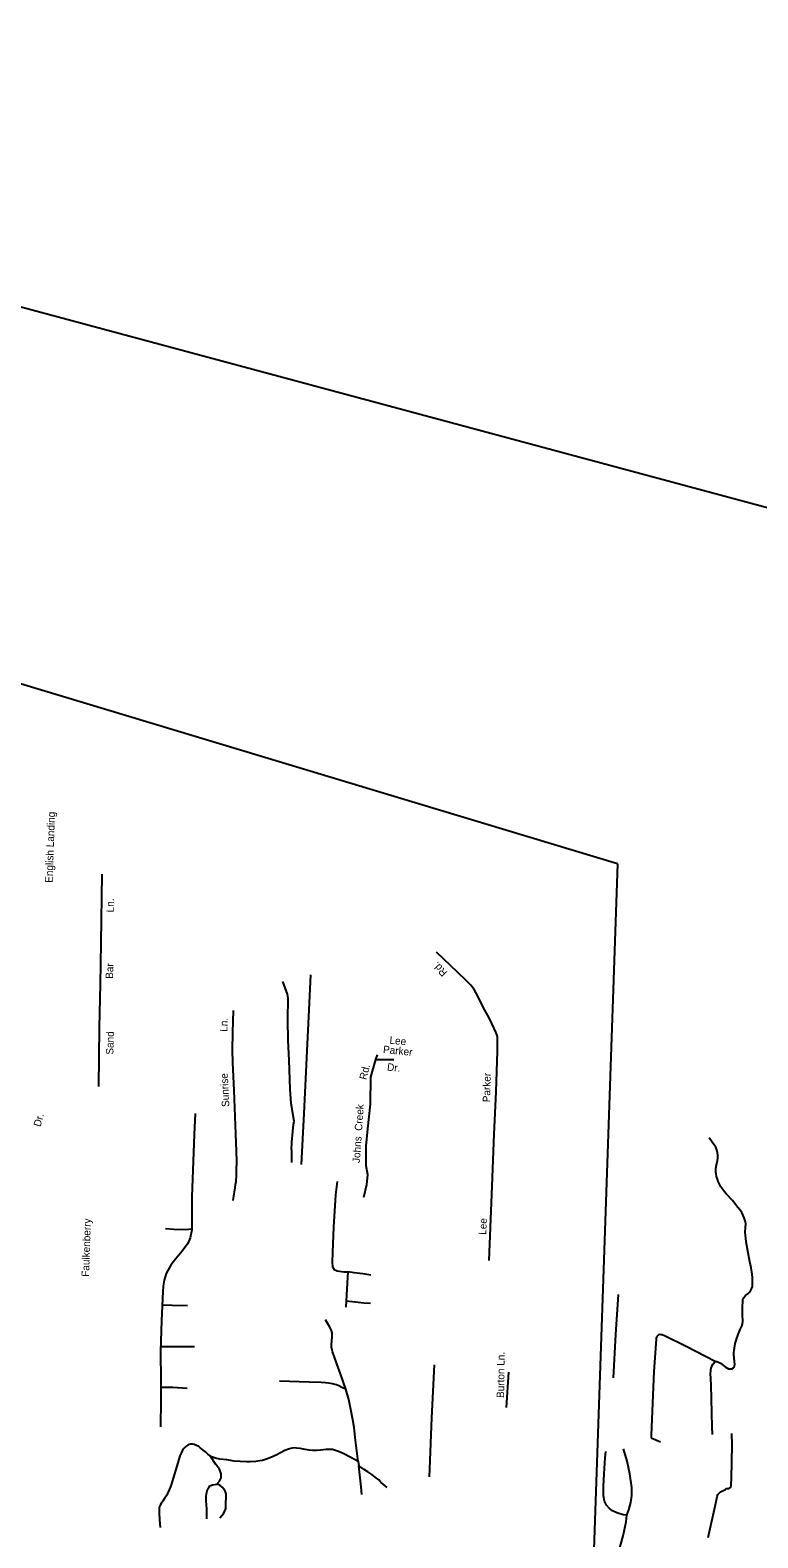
# Model space of a CAD drawing. Extents: x 2308163 to 2335412, y -96774 to 125428.
# Drawn here: x 2320371 to 2321170, y 14013 to 15668 of the extents above; entities that cross this region are included whole.
import ezdxf

# ---------------------------------------------------------------- set-up
doc = ezdxf.new("R2010")
doc.units = 0
for name, color, linetype in [('Old_Level_10', 7, 'Continuous'), ('Old_Level_35', 7, 'Continuous'), ('Old_Level_63', 7, 'Continuous')]:
    doc.layers.add(name, color=color, linetype=linetype)

msp = doc.modelspace()

# ---------------------------------------------------------------- linework, layer by layer
at = {"layer": 'Old_Level_35'}
for p, q in [((2321052.8, 14125.9), (2321052.7, 14123)), ((2321052.7, 14123), (2321063.1, 14118.8)), ((2321119.9, 14126.6), (2321119.6, 14135.1)), ((2320731.1, 14097), (2320731.8, 14092.3)), ((2320734.4, 14069.4), (2320731.8, 14092.3)), ((2320809.5, 14080.2), (2320809.8, 14088.9)), ((2320735.3, 14060.9), (2320734.4, 14069.4)), ((2320513.4, 14033.1), (2320513.8, 14024.7))]:
    msp.add_line(p, q, dxfattribs=at)
for points in [[(2320446.5, 14508.6), (2320447.5, 14573.6), (2320448.4, 14621.1), (2320449.3, 14666.6), (2320450.3, 14741.8)], [(2320874.8, 14317.9), (2320877.8, 14390.1), (2320880.4, 14456.3), (2320882.6, 14503), (2320884.1, 14547.5), (2320884.1, 14551.2), (2320884.1, 14555.6), (2320884.2, 14560), (2320884, 14563), (2320883.6, 14564.8), (2320882.4, 14568.3), (2320880.5, 14572.6), (2320875.2, 14583.3), (2320870.2, 14592.6), (2320860.4, 14612.1), (2320858.6, 14615.4), (2320854.9, 14620), (2320849.5, 14625.6), (2320840.7, 14633.9), (2320817, 14656.2)], [(2320658.3, 14425.4), (2320658.3, 14437.2), (2320658.2, 14441.9), (2320658.5, 14444.9), (2320658.6, 14447.7), (2320659.6, 14459.4), (2320660.1, 14466.9), (2320660.9, 14470.9), (2320657.8, 14490.2), (2320656.7, 14506), (2320655.5, 14537.8), (2320654.3, 14559.3), (2320653.9, 14582.3), (2320654.4, 14605.8), (2320653.5, 14610.1), (2320648.6, 14624)], [(2320669.2, 14423.2), (2320671.9, 14479), (2320675.3, 14548), (2320677.4, 14592.9), (2320679.1, 14631.4)], [(2320596.8, 14456.7), (2320595.2, 14504.5), (2320593.7, 14535), (2320593.2, 14548.6), (2320593.7, 14568), (2320594.5, 14592.3)], [(2320752, 14543.7), (2320750.3, 14538.4), (2320747.4, 14528.3), (2320744.8, 14518.9), (2320744.4, 14489.4), (2320741.6, 14462.2), (2320739.7, 14443.3), (2320739.6, 14422.1), (2320741.5, 14412.2), (2320740.4, 14400.8), (2320736.9, 14386.8)], [(2320750.3, 14538.4), (2320770.3, 14538.3)], [(2320552.3, 14479.2), (2320551.1, 14455.9), (2320548.8, 14387.6), (2320548.6, 14360.5), (2320548.6, 14351.6), (2320546.9, 14342.5), (2320544.2, 14336.4), (2320538.2, 14328.1), (2320530.7, 14319.1), (2320525.5, 14312.8), (2320520.6, 14303.6), (2320518.5, 14296), (2320517.1, 14289.7), (2320516.9, 14283.6), (2320515.4, 14251.7), (2320514.4, 14217.7), (2320514.7, 14185.6), (2320514.7, 14164.3), (2320514.4, 14135.1)], [(2320594, 14383.7), (2320595.2, 14390.9), (2320596.4, 14397.4), (2320596.7, 14401.2), (2320597.3, 14404.4), (2320597.7, 14411.9), (2320597.8, 14417.1), (2320598.1, 14426.8), (2320597.8, 14437.4), (2320596.8, 14456.7)], [(2321123, 14206.8), (2321123.7, 14206.8), (2321124.8, 14206.9), (2321126.5, 14206.3), (2321128.7, 14205.2), (2321130.2, 14203.9), (2321133.9, 14201.1), (2321135.8, 14199.8), (2321137.5, 14199), (2321139.5, 14198.7), (2321141.3, 14198.9), (2321142.9, 14199.9), (2321143.6, 14200.8), (2321144.1, 14202.2), (2321144.5, 14203.6), (2321143.4, 14214.1), (2321143.5, 14216.9), (2321143.6, 14218.9), (2321144.4, 14224.1), (2321145, 14226.6), (2321145.8, 14230.1), (2321146.6, 14232.5), (2321147.7, 14235.3), (2321149, 14238.5), (2321150.5, 14241.9), (2321152.2, 14245.7), (2321153, 14248.4), (2321153.3, 14250.7), (2321153.1, 14252.7), (2321153, 14256.9), (2321152.9, 14261.4), (2321153, 14267.4), (2321153.1, 14272.4), (2321153.4, 14274.4), (2321153.6, 14276), (2321154.3, 14277.3), (2321156.3, 14279.3), (2321158.6, 14281.3), (2321160.4, 14283), (2321161.9, 14285.2), (2321163, 14287.3), (2321163.7, 14289.3), (2321163.9, 14291.9), (2321163.9, 14294.7), (2321163.7, 14298.7), (2321163.4, 14302.7), (2321162.3, 14309.7), (2321160.9, 14316.2), (2321159.2, 14326.3), (2321156.9, 14338.4), (2321156.4, 14342.2), (2321156.1, 14345.1), (2321156, 14348.9), (2321156.3, 14354.1), (2321156.4, 14357.9), (2321156.2, 14360.1), (2321155.5, 14362.4), (2321154.7, 14364.5), (2321153.6, 14367), (2321152, 14370.3), (2321150.3, 14373), (2321147.9, 14376.1), (2321142, 14383.5), (2321135.4, 14390.6), (2321133.3, 14393.2), (2321131.3, 14395.7), (2321129.2, 14398.8), (2321127.6, 14401.5), (2321126.2, 14404.5), (2321125.4, 14406.9), (2321124.4, 14410.1), (2321124, 14412.9), (2321123.8, 14414.9), (2321123.8, 14418.7), (2321124.2, 14422.7), (2321125.3, 14427.7), (2321125.8, 14430.1), (2321125.9, 14433.5), (2321125.5, 14435.9), (2321124.6, 14439.4), (2321123.7, 14442.2), (2321119.6, 14447.8), (2321116.2, 14452.6)], [(2320708, 14404.3), (2320706.4, 14390), (2320704.2, 14354.3), (2320702.9, 14327), (2320702.6, 14316), (2320703, 14310.8), (2320704.9, 14307.8), (2320708.1, 14306.4), (2320715.5, 14305.4), (2320719.8, 14305.3)], [(2320548.6, 14352.3), (2320542, 14351.4), (2320528.9, 14351.8), (2320519.7, 14352.6)], [(2320719.8, 14305.3), (2320718.8, 14286.8), (2320717.5, 14266.7)], [(2320745, 14301.8), (2320736.3, 14303.1), (2320726.9, 14304.1), (2320719.8, 14305.3)], [(2320516.2, 14268.9), (2320527.3, 14268.8), (2320543.9, 14268.2)], [(2320717.9, 14273.3), (2320728.4, 14272.5), (2320737.5, 14271.2), (2320744.6, 14271)], [(2321011.5, 14189), (2321013.9, 14236.5), (2321016.7, 14280.5)], [(2320717.8, 14176.4), (2320712, 14193.3), (2320707.7, 14204.2), (2320704.7, 14212.6), (2320703.6, 14215.8), (2320703.1, 14218), (2320702.7, 14219.3), (2320702.1, 14222.5), (2320702, 14225.6), (2320702.3, 14229.5), (2320702.7, 14233.5), (2320702.7, 14235.8), (2320702.5, 14238.2), (2320701.9, 14240.8), (2320700.2, 14244.6), (2320697.5, 14248.9), (2320695.2, 14252.5)], [(2321123, 14206.8), (2321091.1, 14223.4), (2321067.4, 14235), (2321064.9, 14236), (2321063.7, 14236.3), (2321062.3, 14236.4), (2321060.7, 14236), (2321059.6, 14235.1), (2321058.9, 14234.2), (2321058.3, 14232.5), (2321058.3, 14231.4), (2321055.7, 14196), (2321052.8, 14125.9)], [(2320514.6, 14223.2), (2320525.8, 14223.4), (2320551.6, 14223.4)], [(2320809.8, 14088.9), (2320812.1, 14144.9), (2320814.8, 14203.3)], [(2321119.6, 14135.1), (2321118.4, 14181.2), (2321117.9, 14194), (2321118, 14196.2), (2321118.1, 14198.1), (2321118.8, 14200.5), (2321119.6, 14202.2), (2321120.4, 14203.9), (2321123, 14206.8)], [(2320717.8, 14176.4), (2320713.4, 14178.5), (2320710.1, 14180.1), (2320707.6, 14181.1), (2320702.9, 14182.5), (2320698.7, 14183.1), (2320695.2, 14183.4), (2320690.5, 14183.8), (2320677.5, 14184.1), (2320645, 14185.2)], [(2320894, 14156.3), (2320896.5, 14195)], [(2320543.4, 14177.3), (2320527.7, 14178.3), (2320514.7, 14178.4)], [(2320731.1, 14097), (2320727.8, 14123.6), (2320726.8, 14134.4), (2320725.5, 14142.7), (2320723.3, 14154.3), (2320720.8, 14165.3), (2320717.8, 14176.4)], [(2321115.3, 14013.7), (2321123.7, 14051.5), (2321125, 14058.7), (2321126, 14061), (2321127.5, 14062.7), (2321128.8, 14063.7), (2321130.1, 14064.4), (2321132.1, 14065.3), (2321134.1, 14066.3), (2321135.6, 14067.3), (2321136.2, 14067.4), (2321137.6, 14067.6), (2321139, 14068.2), (2321140, 14069), (2321140.4, 14071.2), (2321141, 14078.9), (2321141.7, 14114.9), (2321141.1, 14128)], [(2320563.8, 14107.6), (2320561.1, 14109.7), (2320559.1, 14111.2), (2320557.9, 14112.2), (2320556.2, 14113.5), (2320553.9, 14114.7), (2320551.2, 14115.6), (2320549.7, 14116.1), (2320547.3, 14116.2), (2320545.8, 14115.8), (2320544.2, 14115.1), (2320542.2, 14113.6), (2320539.9, 14111.4), (2320538.6, 14109.7), (2320537.2, 14106.8), (2320535.7, 14103.3), (2320533.3, 14095.8), (2320527.3, 14075.2), (2320525.6, 14070.3), (2320523.9, 14065.8), (2320522, 14061.8), (2320521.1, 14060.1), (2320518.8, 14056.4), (2320516.7, 14053.4), (2320515.2, 14051), (2320513.9, 14049.2), (2320513.3, 14047.8), (2320512.8, 14045.8), (2320512.7, 14044.1), (2320512.9, 14040.8), (2320513.4, 14033.1)], [(2320731.1, 14097), (2320723.3, 14101.3), (2320714.8, 14105.7), (2320709.6, 14108.1), (2320705.4, 14109.7), (2320703, 14110.3), (2320700, 14110.3), (2320696.2, 14110.1), (2320689.9, 14109.5), (2320685.4, 14109.3), (2320681.1, 14109.2), (2320677.4, 14109.6), (2320672.9, 14110.2), (2320667.7, 14111.3), (2320663.5, 14111.9), (2320660.4, 14112), (2320657.4, 14111.3), (2320654.9, 14110.6), (2320650.7, 14109), (2320646.1, 14106.6), (2320642, 14104.5), (2320638, 14102.5), (2320633.7, 14100.6), (2320630.7, 14099.5), (2320626.4, 14098.3), (2320623.4, 14097.9), (2320619.1, 14097.2), (2320612.8, 14096.8), (2320608.7, 14096.8), (2320601.6, 14097), (2320595.1, 14097.6), (2320587.1, 14098.8), (2320579.4, 14099.7), (2320574.6, 14100.6), (2320572.5, 14101.3), (2320570.4, 14102.2), (2320568.7, 14103.2), (2320566.3, 14105), (2320563.8, 14107.6)], [(2320579.5, 14035.2), (2320583.9, 14040.2), (2320585.9, 14045.4), (2320586.1, 14052.2), (2320586.4, 14056.9), (2320586.5, 14059.4), (2320586.5, 14061.5), (2320586.1, 14062.7), (2320585.2, 14064.6), (2320583.8, 14066.7), (2320581.9, 14069), (2320579.6, 14071.2), (2320576, 14072.2), (2320579, 14075.4), (2320581, 14079), (2320581, 14083.5), (2320579.2, 14088.8), (2320575.2, 14093.7), (2320568.7, 14103.2)], [(2321026.1, 14038.3), (2321021.9, 14038.5), (2321014.9, 14040.6), (2321010.2, 14043.1), (2321007, 14045.6), (2321003.8, 14049), (2321001.6, 14053.4), (2321000.4, 14059.5), (2321000.3, 14069.5), (2321001.2, 14083.6), (2321002.3, 14101), (2321003.1, 14108.1)], [(2321026.1, 14038.3), (2321028.2, 14043.9), (2321030.4, 14051.9), (2321031.6, 14059.9), (2321031.4, 14068.4), (2321029.1, 14083.6), (2321026.3, 14097.3), (2321022.4, 14111)], [(2320755.3, 14075.3), (2320753.7, 14076.8), (2320749.9, 14079.9), (2320746.3, 14082.7), (2320741.9, 14085.8), (2320737.7, 14088.4), (2320731.8, 14092.3)], [(2320565.1, 14034.1), (2320565.3, 14045.2), (2320564.5, 14053.9), (2320564.6, 14059.2), (2320565, 14063.4), (2320565.8, 14066.2), (2320567.2, 14068.7), (2320568.5, 14070.5), (2320571.3, 14071.6), (2320576, 14072.2)], [(2320763.1, 14068.7), (2320756.6, 14074.2), (2320755.3, 14075.3)], [(2321014.3, 13982.6), (2321016.1, 13994.8), (2321022, 14015.4), (2321025.4, 14030.8), (2321026.1, 14038.3)]]:
    msp.add_lwpolyline(points, dxfattribs=at)
at = {"layer": 'Old_Level_63'}
msp.add_line((2321015.8, 14753.3), (2319999.6, 15059.8), dxfattribs=at)
for points in [[(2322610.8, 14711), (2322280.6, 14847.9), (2319230.7, 15668.5)], [(2321015.8, 14753.3), (2320959.2, 13110.3), (2319933.5, 13142.7), (2319999.6, 15059.8)]]:
    msp.add_lwpolyline(points, dxfattribs=at)

# ---------------------------------------------------------------- texts
at = {"layer": 'Old_Level_10'}
for s, height, rotation, p in [('English Landing', 8.202, 88.0247, (2320395.9, 14732.3)), ('Ln.', 8.2, 89.0989, (2320463, 14699.9)), ('Bar', 8.2, 88.1197, (2320462.2, 14626.9)), ('Rd.', 8.2, 132.9634, (2320829.7, 14634.2)), ('Ln.', 8.2, 88.0624, (2320587.6, 14568.8)), ('Sand', 8.2, 88.9158, (2320462.6, 14543.7)), ('Parker', 8.2, 354.2925, (2320758.2, 14545.6)), ('Lee', 8.2, 354.2925, (2320765.3, 14555.8)), ('Dr.', 8.2, 354.2925, (2320762.6, 14526.3)), ('Sunrise', 8.2, 92.8193, (2320589.9, 14486.5)), ('Rd.', 8.2, 76.1913, (2320740.2, 14515.6)), ('Parker', 8.2, 88.7193, (2320876, 14491.4)), ('Johns  Creek ', 8.202, 86.0484, (2320733, 14424.6)), ('Dr.', 8.2, 74.2787, (2320382.6, 14464)), ('Faulkenberry', 8.202, 88.1377, (2320435.9, 14299.8)), ('Lee', 8.2, 86.8925, (2320871.6, 14345.8)), ('Burton Ln.', 8.2, 89.2977, (2320891.3, 14166.8))]:
    msp.add_text(s, height=height, rotation=rotation, dxfattribs=at).set_placement(p)

doc.saveas('drawing.dxf')
